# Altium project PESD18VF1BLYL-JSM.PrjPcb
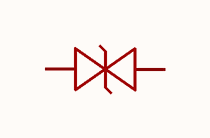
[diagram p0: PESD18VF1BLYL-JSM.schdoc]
1 sheet, 1 parts. Net scope: global (net labels, ports and power ports of the same name join across sheets).

## Sheet PESD18VF1BLYL-JSM.schdoc
size 127 x 101 mm

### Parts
D?  pesd18vf1blyl-jsm  [DFN1006-2L-BI-1]  (value not drawn)

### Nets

Not connected (* = marked no-connect by the designer): D? 1 2

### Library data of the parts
D? = pesd18vf1blyl-jsm: 极性:-;反向工作电压(Vrwm):18V;钳位电压:32V;峰值脉冲电流(Ipp):1A@8/20us;峰值脉冲功率(Ppp):32W@8/20us;击穿电压(VBR):23V;; Manufacturer: JSMSEMI(杰盛微); AddInBom: yes; ModelId: 4f73e746f3be4d299816d29f03249d6e; ModelTransform: 40.1574,24.4094,0,0,0,0,0,0,0; Reverse Stand-Off Voltage (Vrwm): 18V; Clamping Voltage: 32V; Voltage - Breakdown: 23V; Reverse Leakage Current (Ir): 100nA; Number of Channels: 单路; level of protection: IEC 61000-4-2; Type: ESD; Junction Capacitance: 0.45pF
